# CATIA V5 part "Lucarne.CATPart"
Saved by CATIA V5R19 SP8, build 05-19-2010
Part number: Lucarne
Revision: ANY
Definition: UNKNOWN
Nomenclature: Lucarne
Source: Unknown
Bounding box of the stored display mesh (mm): x -290 to 290, y -290 to 290, z 0 to 5
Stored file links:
  D:\Documents\1_Travail\1 - ac-limoges.fr\OneDrive - ac-limoges.fr\STI2D_Turgot\2 -2I2D\3_SEQUENCE_Serre_Connectée\3- Spécificités\ITEC\EC 3 Ouverture automatique\Simulation  Ouverture Automatique\Lucarne.CATPart
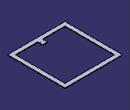
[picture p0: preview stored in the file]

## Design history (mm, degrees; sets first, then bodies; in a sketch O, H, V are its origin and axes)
Body1 "NONE" (main body)
  Solid1: solid without history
